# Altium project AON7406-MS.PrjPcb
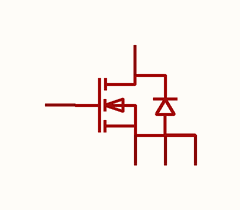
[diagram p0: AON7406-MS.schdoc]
1 sheet, 1 parts. Net scope: global (net labels, ports and power ports of the same name join across sheets).

## Sheet AON7406-MS.schdoc
size 127 x 101 mm

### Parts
Q?  aon7406-ms  [PDFN3333-8_L3.1-W3.2-P0.65-LS3.4-BL_1]  (value not drawn)

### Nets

Not connected (* = marked no-connect by the designer): Q? 1(S) 2(S) 3(S) 4(G) 5(D)

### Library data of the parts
Q? = aon7406-ms: 数量:1个N沟道;漏源电压(Vdss):30V;连续漏极电流(Id):-;导通电阻(RDS(on)):15mΩ@10V;耗散功率(Pd):5.5W;阈值电压(Vgs(th)):1.5V;; Manufacturer: MSKSEMI(美森科); AddInBom: yes; ModelId: c288237aeb774e1d92142cc9eea176d4; ModelTransform: 118.8974,118.8974,0,90,0,0,0,19.486,0; Number: 1个N沟道; Drain to Source Voltage: 30V; Pd - Power Dissipation: 5.5W; Gate Threshold Voltage (Vgs(th)): 1.5V; Gate Charge(Qg): 10nC; Input Capacitance(Ciss): 490pF; Reverse Transfer Capacitance (Crss@Vds): 61pF; Type: N沟道; Output Capacitance(Coss): 79pF; Vgs: ±20V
